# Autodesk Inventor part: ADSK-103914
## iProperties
Shininess: 0.0
Created: 2000-10
Part Number: ADSK-103914
Document SubType Name: Modeling
Stock Number: ADSK-103914
Density: 1 g/cm^3
Density: 0.0
Volumn: 0.0
Area: 0.0
PropertySet Name: Model Information
Control State: 0
Master: False
Checked Out: False
Author: gao
